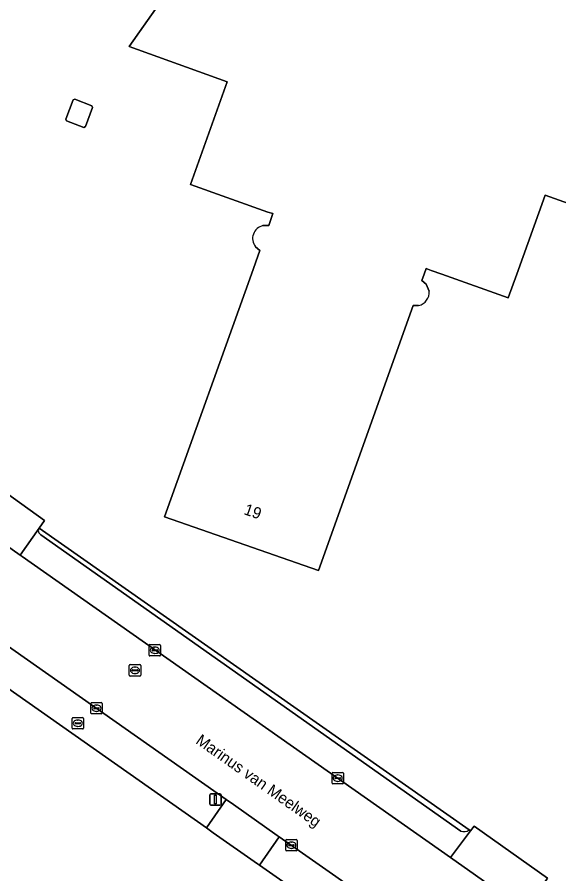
# Model space of a CAD drawing. Extents: x 155018 to 156648, y 383979 to 385733.
# Drawn here: x 155513.9 to 155561.5, y 384947.3 to 385022.6 of the extents above; entities that cross this region are included whole.
import ezdxf

# ---------------------------------------------------------------- set-up
doc = ezdxf.new("R2010")
doc.units = 0
for name, color, linetype in [('IMGEO_Brandkraan', 7, 'Continuous'), ('IMGEO_Erf', 7, 'Continuous'), ('IMGEO_Kolk', 7, 'Continuous'), ('IMGEO_Lichtmast', 7, 'Continuous'), ('IMGEO_Openbare_ruimte_label', 7, 'Continuous'), ('IMGEO_Pand', 7, 'Continuous'), ('IMGEO_Pand_nummerreeks', 7, 'Continuous'), ('IMGEO_Parkeervlak_open', 7, 'Continuous'), ('IMGEO_Rijbaan_lokaal_gesloten', 7, 'Continuous'), ('IMGEO_Rioolput', 7, 'Continuous'), ('IMGEO_Voetpad_open', 7, 'Continuous')]:
    doc.layers.add(name, color=color, linetype=linetype)

msp = doc.modelspace()

# ---------------------------------------------------------------- linework, layer by layer
at = {"layer": 'IMGEO_Brandkraan'}
for p, q in [((155518.686, 384960.086), (155518.686, 384960.938)), ((155518.761, 384961.012), (155519.613, 384961.012)), ((155518.945, 384960.506), (155518.945, 384960.518)), ((155518.988, 384960.555), (155519.386, 384960.555)), ((155519.174, 384960.792), (155519.199, 384960.792)), ((155519.429, 384960.518), (155519.429, 384960.506)), ((155519.687, 384960.938), (155519.687, 384960.086)), ((155519.613, 384960.012), (155518.761, 384960.012)), ((155519.383, 384960.469), (155518.985, 384960.469)), ((155519.197, 384960.232), (155519.172, 384960.232))]:
    msp.add_line(p, q, dxfattribs=at)
for points in [[(155518.686, 384960.086), (155518.686, 384960.938)], [(155518.761, 384961.012), (155519.613, 384961.012)], [(155519.687, 384960.938), (155519.687, 384960.086)], [(155519.613, 384960.012), (155518.761, 384960.012)]]:
    msp.add_lwpolyline(points, dxfattribs=at)
for centre, radius, start, end in [((155518.763, 384960.936), 0.0765, 91.55205, 178.44795), ((155518.763, 384960.936), 0.0765, 91.55205, 178.44795), ((155518.985, 384960.515), 0.0403, 85.87752, 175.75265), ((155518.982, 384960.505), 0.0366, 178.93798, 274.71019), ((155519.386, 384960.512), 0.043, 264.86636, 352.45326), ((155519.39, 384960.517), 0.0386, 1.73085, 96.63898), ((155519.611, 384960.936), 0.0765, 1.55205, 88.44795), ((155519.611, 384960.936), 0.0765, 1.55205, 88.44795), ((155518.763, 384960.088), 0.0765, 181.55205, 268.44795), ((155518.763, 384960.088), 0.0765, 181.55205, 268.44795), ((155519.611, 384960.088), 0.0765, 271.55205, 358.44795), ((155519.611, 384960.088), 0.0765, 271.55205, 358.44795)]:
    msp.add_arc(centre, radius, start, end, dxfattribs=at)
for centre, major_axis, ratio, start_param, end_param in [((155519.173, 384960.512), (-0.387, 0.002), 0.722429, 4.712389, 7.853982), ((155519.198, 384960.512), (-0.39, 0.002), 0.717154, 1.570796, 4.712389)]:
    msp.add_ellipse(centre, major_axis=major_axis, ratio=ratio, start_param=start_param, end_param=end_param, dxfattribs=at)
at = {"layer": 'IMGEO_Erf'}
for points in [[(155535.473, 385004.273), (155535.985, 385004.271), (155536.336, 385005.323), (155535.896, 385005.456), (155529.096, 385007.886), (155532.322, 385016.918), (155523.708, 385020.015), (155526.582, 385024.107), (155553.008, 385061.731), (155555.772, 385060.745), (155568.458, 385096.335), (155630.019, 385074.396), (155603.521, 385000)], [(155457.525, 385018.63), (155458.619, 385017.864), (155484.145, 385000), (155491.64, 384994.721), (155500, 384988.865), (155510.83, 384981.203), (155511.294, 384981.88), (155516.258, 384978.35), (155515.775, 384977.663), (155553.601, 384951.142), (155553.738, 384951.046), (155554.058, 384951.47), (155560.497, 384946.89), (155560.229, 384946.497), (155580.857, 384931.994), (155586.597, 384927.958), (155607.46, 384913.427), (155617.317, 384906.512), (155620.874, 384904.014), (155651.48, 384882.509)], [(155645.703, 384870.176), (155613.715, 384892.628), (155600.657, 384901.793), (155582.308, 384914.778), (155574.917, 384919.981), (155570.133, 384923.483), (155539.854, 384944.743), (155535.161, 384948.038), (155534.984, 384948.163), (155531.101, 384950.889), (155530.5, 384951.311), (155510.828, 384965.124), (155506.264, 384968.328), (155505.588, 384968.803), (155501.395, 384971.747), (155500, 384972.727), (155492.047, 384978.311), (155491.266, 384978.86), (155482.605, 384984.76), (155482.381, 384984.92), (155460.927, 385000), (155450.653, 385007.222)], [(155603.521, 385000), (155602.521, 384997.193), (155600.843, 384992.482), (155579.769, 385000), (155560.285, 385006.951), (155557.797, 385000), (155557.05, 384997.913), (155551.193, 385000), (155550.264, 385000.331), (155549.839, 385000.497), (155549.65, 385000), (155549.437, 384999.439), (155549.832, 384999.123), (155550.085, 384998.504)], [(155549.161, 384997.245), (155548.687, 384997.244), (155540.351, 384973.929), (155526.816, 384978.65), (155534.46, 385000), (155535.208, 385002.089), (155534.809, 385002.413)]]:
    msp.add_lwpolyline(points, dxfattribs=at)
msp.add_lwpolyline([(155519.719, 385012.905), (155518.205, 385013.48), (155518.128, 385013.619), (155518.771, 385015.316), (155518.938, 385015.371), (155520.419, 385014.813), (155520.474, 385014.663), (155519.862, 385012.978)], close=True, dxfattribs=at)
for centre, radius, start, end in [((155535.726, 385003.134), 1.166, 102.51087, 218.19709), ((155548.923, 384998.389), 1.168, 281.77899, 5.66994)]:
    msp.add_arc(centre, radius, start, end, dxfattribs=at)
at = {"layer": 'IMGEO_Kolk'}
for p, q in [((155525.454, 384966.504), (155525.454, 384967.356)), ((155525.529, 384967.43), (155526.381, 384967.43)), ((155526.455, 384967.356), (155526.455, 384966.504)), ((155525.713, 384966.924), (155525.713, 384966.936)), ((155526.151, 384966.887), (155525.753, 384966.887)), ((155525.756, 384966.973), (155526.154, 384966.973)), ((155525.965, 384966.65), (155525.94, 384966.65)), ((155525.942, 384967.21), (155525.967, 384967.21)), ((155526.197, 384966.936), (155526.197, 384966.924)), ((155526.381, 384966.43), (155525.529, 384966.43)), ((155520.325, 384961.408), (155520.325, 384962.26)), ((155520.4, 384962.334), (155521.252, 384962.334)), ((155520.813, 384962.114), (155520.838, 384962.114)), ((155521.326, 384962.26), (155521.326, 384961.408)), ((155521.252, 384961.334), (155520.4, 384961.334)), ((155520.584, 384961.828), (155520.584, 384961.84)), ((155521.022, 384961.791), (155520.624, 384961.791)), ((155520.627, 384961.877), (155521.025, 384961.877)), ((155520.836, 384961.554), (155520.811, 384961.554)), ((155521.068, 384961.84), (155521.068, 384961.828)), ((155541.547, 384955.257), (155541.547, 384956.109)), ((155541.622, 384956.183), (155542.474, 384956.183)), ((155542.548, 384956.109), (155542.548, 384955.257)), ((155541.806, 384955.677), (155541.806, 384955.689)), ((155542.244, 384955.64), (155541.846, 384955.64)), ((155541.849, 384955.726), (155542.247, 384955.726)), ((155542.058, 384955.403), (155542.033, 384955.403)), ((155542.035, 384955.963), (155542.06, 384955.963)), ((155542.29, 384955.689), (155542.29, 384955.677)), ((155542.474, 384955.183), (155541.622, 384955.183)), ((155537.472, 384949.363), (155537.472, 384950.215)), ((155537.547, 384950.289), (155538.399, 384950.289)), ((155537.96, 384950.069), (155537.985, 384950.069)), ((155538.473, 384950.215), (155538.473, 384949.363)), ((155538.399, 384949.289), (155537.547, 384949.289)), ((155537.731, 384949.783), (155537.731, 384949.795)), ((155538.169, 384949.746), (155537.771, 384949.746)), ((155537.774, 384949.832), (155538.172, 384949.832)), ((155537.983, 384949.509), (155537.958, 384949.509)), ((155538.215, 384949.795), (155538.215, 384949.783))]:
    msp.add_line(p, q, dxfattribs=at)
for points in [[(155525.454, 384966.504), (155525.454, 384967.356)], [(155525.529, 384967.43), (155526.381, 384967.43)], [(155526.455, 384967.356), (155526.455, 384966.504)], [(155526.381, 384966.43), (155525.529, 384966.43)], [(155520.325, 384961.408), (155520.325, 384962.26)], [(155520.4, 384962.334), (155521.252, 384962.334)], [(155521.326, 384962.26), (155521.326, 384961.408)], [(155521.252, 384961.334), (155520.4, 384961.334)], [(155541.547, 384955.257), (155541.547, 384956.109)], [(155541.622, 384956.183), (155542.474, 384956.183)], [(155542.548, 384956.109), (155542.548, 384955.257)], [(155542.474, 384955.183), (155541.622, 384955.183)], [(155537.472, 384949.363), (155537.472, 384950.215)], [(155537.547, 384950.289), (155538.399, 384950.289)], [(155538.473, 384950.215), (155538.473, 384949.363)], [(155538.399, 384949.289), (155537.547, 384949.289)]]:
    msp.add_lwpolyline(points, dxfattribs=at)
for centre, radius, start, end in [((155525.531, 384967.354), 0.0765, 91.55205, 178.44795), ((155525.531, 384967.354), 0.0765, 91.55205, 178.44795), ((155526.379, 384967.354), 0.0765, 1.55205, 88.44795), ((155526.379, 384967.354), 0.0765, 1.55205, 88.44795), ((155525.753, 384966.933), 0.0403, 85.87752, 175.75265), ((155525.75, 384966.923), 0.0366, 178.93798, 274.71019), ((155526.154, 384966.93), 0.043, 264.86636, 352.45326), ((155526.158, 384966.935), 0.0386, 1.73085, 96.63898), ((155525.531, 384966.506), 0.0765, 181.55205, 268.44795), ((155525.531, 384966.506), 0.0765, 181.55205, 268.44795), ((155526.379, 384966.506), 0.0765, 271.55205, 358.44795), ((155526.379, 384966.506), 0.0765, 271.55205, 358.44795), ((155520.402, 384962.258), 0.0765, 91.55205, 178.44795), ((155520.402, 384962.258), 0.0765, 91.55205, 178.44795), ((155521.25, 384962.258), 0.0765, 1.55205, 88.44795), ((155521.25, 384962.258), 0.0765, 1.55205, 88.44795), ((155520.402, 384961.41), 0.0765, 181.55205, 268.44795), ((155520.402, 384961.41), 0.0765, 181.55205, 268.44795), ((155520.624, 384961.837), 0.0403, 85.87752, 175.75265), ((155520.621, 384961.827), 0.0366, 178.93798, 274.71019), ((155521.025, 384961.834), 0.043, 264.86636, 352.45326), ((155521.029, 384961.839), 0.0386, 1.73085, 96.63898), ((155521.25, 384961.41), 0.0765, 271.55205, 358.44795), ((155521.25, 384961.41), 0.0765, 271.55205, 358.44795), ((155541.624, 384956.107), 0.0765, 91.55205, 178.44795), ((155541.624, 384956.107), 0.0765, 91.55205, 178.44795), ((155542.472, 384956.107), 0.0765, 1.55205, 88.44795), ((155542.472, 384956.107), 0.0765, 1.55205, 88.44795), ((155541.624, 384955.259), 0.0765, 181.55205, 268.44795), ((155541.624, 384955.259), 0.0765, 181.55205, 268.44795), ((155541.846, 384955.686), 0.0403, 85.87752, 175.75265), ((155541.843, 384955.676), 0.0366, 178.93798, 274.71019), ((155542.247, 384955.683), 0.043, 264.86636, 352.45326), ((155542.251, 384955.688), 0.0386, 1.73085, 96.63898), ((155542.472, 384955.259), 0.0765, 271.55205, 358.44795), ((155542.472, 384955.259), 0.0765, 271.55205, 358.44795), ((155537.549, 384950.213), 0.0765, 91.55205, 178.44795), ((155537.549, 384950.213), 0.0765, 91.55205, 178.44795), ((155538.397, 384950.213), 0.0765, 1.55205, 88.44795), ((155538.397, 384950.213), 0.0765, 1.55205, 88.44795), ((155537.549, 384949.365), 0.0765, 181.55205, 268.44795), ((155537.549, 384949.365), 0.0765, 181.55205, 268.44795), ((155537.771, 384949.792), 0.0403, 85.87752, 175.75265), ((155537.768, 384949.782), 0.0366, 178.93798, 274.71019), ((155538.172, 384949.789), 0.043, 264.86636, 352.45326), ((155538.176, 384949.794), 0.0386, 1.73085, 96.63898), ((155538.397, 384949.365), 0.0765, 271.55205, 358.44795), ((155538.397, 384949.365), 0.0765, 271.55205, 358.44795)]:
    msp.add_arc(centre, radius, start, end, dxfattribs=at)
for centre, major_axis, ratio, start_param, end_param in [((155525.941, 384966.93), (-0.387, 0.002), 0.722429, 4.712389, 7.853982), ((155525.966, 384966.93), (-0.39, 0.002), 0.717154, 1.570796, 4.712389), ((155520.812, 384961.834), (-0.387, 0.002), 0.722429, 4.712389, 7.853982), ((155520.837, 384961.834), (-0.39, 0.002), 0.717154, 1.570796, 4.712389), ((155542.034, 384955.683), (-0.387, 0.002), 0.722429, 4.712389, 7.853982), ((155542.059, 384955.683), (-0.39, 0.002), 0.717154, 1.570796, 4.712389), ((155537.959, 384949.789), (-0.387, 0.002), 0.722429, 4.712389, 7.853982), ((155537.984, 384949.789), (-0.39, 0.002), 0.717154, 1.570796, 4.712389)]:
    msp.add_ellipse(centre, major_axis=major_axis, ratio=ratio, start_param=start_param, end_param=end_param, dxfattribs=at)
at = {"layer": 'IMGEO_Lichtmast'}
for p, q in [((155530.797, 384953.402), (155530.797, 384954.202)), ((155530.797, 384954.202), (155530.797, 384953.402)), ((155530.897, 384954.302), (155531.687, 384954.302)), ((155531.687, 384954.302), (155530.897, 384954.302)), ((155531.787, 384954.202), (155531.787, 384953.402)), ((155531.787, 384953.402), (155531.787, 384954.202)), ((155531.687, 384953.302), (155530.897, 384953.302)), ((155530.897, 384953.302), (155531.687, 384953.302))]:
    msp.add_line(p, q, dxfattribs=at)
msp.add_lwpolyline([(155531.217, 384954.177), (155531.367, 384954.177), (155531.367, 384953.427), (155531.217, 384953.427), (155531.217, 384954.177)], dxfattribs=at)
for centre, start, end in [((155530.897, 384954.202), 90, 180), ((155530.897, 384954.202), 90, 180), ((155531.687, 384954.202), 0, 90), ((155531.687, 384954.202), 360, 90), ((155530.897, 384953.402), 180, 270), ((155530.897, 384953.402), 180, 270), ((155531.687, 384953.402), 270, 0), ((155531.687, 384953.402), 270, 0)]:
    msp.add_arc(centre, 0.1, start, end, dxfattribs=at)
at = {"layer": 'IMGEO_Pand'}
for points in [[(155568.458, 385096.335), (155555.772, 385060.745), (155553.008, 385061.731), (155526.582, 385024.107), (155523.708, 385020.015), (155532.322, 385016.918), (155529.096, 385007.886), (155535.896, 385005.456), (155536.336, 385005.323), (155535.985, 385004.271), (155535.473, 385004.273)], [(155550.085, 384998.504), (155549.832, 384999.123), (155549.437, 384999.439), (155549.65, 385000), (155549.839, 385000.497), (155550.264, 385000.331), (155551.193, 385000), (155557.05, 384997.913), (155557.797, 385000), (155560.285, 385006.951), (155579.769, 385000)], [(155534.809, 385002.413), (155535.208, 385002.089), (155534.46, 385000), (155526.816, 384978.65), (155540.351, 384973.929), (155548.687, 384997.244), (155549.161, 384997.245)]]:
    msp.add_lwpolyline(points, dxfattribs=at)
msp.add_lwpolyline([(155519.719, 385012.905), (155519.862, 385012.978), (155520.474, 385014.663), (155520.419, 385014.813), (155518.938, 385015.371), (155518.771, 385015.316), (155518.128, 385013.619), (155518.205, 385013.48)], close=True, dxfattribs=at)
for centre, radius, start, end in [((155535.726, 385003.134), 1.166, 102.51087, 218.19709), ((155548.923, 384998.389), 1.168, 281.77899, 5.66994)]:
    msp.add_arc(centre, radius, start, end, dxfattribs=at)
at = {"layer": 'IMGEO_Parkeervlak_open'}
for points in [[(155515.775, 384977.663), (155514.115, 384975.3), (155514.295, 384975.174), (155551.965, 384948.699), (155553.738, 384951.046), (155553.601, 384951.142)], [(155552.875, 384951.036), (155515.938, 384977.083)]]:
    msp.add_lwpolyline(points, dxfattribs=at)
for centre, radius, start, end in [((155516.12, 384977.447), 0.407, 147.91031, 243.48408), ((155553.157, 384951.645), 0.671, 245.15954, 311.45407)]:
    msp.add_arc(centre, radius, start, end, dxfattribs=at)
at = {"layer": 'IMGEO_Rijbaan_lokaal_gesloten'}
for points in [[(155650.099, 384879.818), (155615.524, 384904.073), (155605.603, 384911.034), (155580.666, 384928.528), (155558.57, 384944.057), (155551.965, 384948.699), (155514.295, 384975.174), (155514.115, 384975.3), (155509.167, 384978.777), (155500, 384985.217), (155489.982, 384992.256), (155489.845, 384992.352), (155482.635, 384997.401), (155478.917, 385000), (155456.1, 385015.949)], [(155452.478, 385009.864), (155466.537, 385000), (155468.855, 384998.374), (155481.303, 384989.599), (155484.226, 384987.538), (155493.798, 384980.798), (155500, 384976.456), (155502.879, 384974.44), (155503.149, 384974.25), (155507.358, 384971.292), (155508.017, 384970.829), (155512.594, 384967.613), (155532.25, 384953.8), (155532.882, 384953.356), (155536.732, 384950.651), (155536.91, 384950.526), (155541.6, 384947.23), (155571.894, 384925.942), (155573.015, 384925.172), (155576.741, 384922.577), (155602.522, 384904.454), (155615.591, 384895.277), (155647.55, 384872.837)]]:
    msp.add_lwpolyline(points, dxfattribs=at)
at = {"layer": 'IMGEO_Rioolput'}
for p, q in [((155523.716, 384964.738), (155523.716, 384965.59)), ((155523.791, 384965.664), (155524.643, 384965.664)), ((155523.975, 384965.158), (155523.975, 384965.17)), ((155524.413, 384965.121), (155524.015, 384965.121)), ((155524.018, 384965.207), (155524.416, 384965.207)), ((155524.204, 384965.444), (155524.229, 384965.444)), ((155524.459, 384965.17), (155524.459, 384965.158)), ((155524.717, 384965.59), (155524.717, 384964.738)), ((155524.643, 384964.664), (155523.791, 384964.664)), ((155524.227, 384964.884), (155524.202, 384964.884))]:
    msp.add_line(p, q, dxfattribs=at)
for points in [[(155523.716, 384964.738), (155523.716, 384965.59)], [(155523.791, 384965.664), (155524.643, 384965.664)], [(155524.717, 384965.59), (155524.717, 384964.738)], [(155524.643, 384964.664), (155523.791, 384964.664)]]:
    msp.add_lwpolyline(points, dxfattribs=at)
for centre, radius, start, end in [((155523.793, 384965.588), 0.0765, 91.55205, 178.44795), ((155523.793, 384965.588), 0.0765, 91.55205, 178.44795), ((155524.015, 384965.167), 0.0403, 85.87752, 175.75265), ((155524.012, 384965.157), 0.0366, 178.93798, 274.71019), ((155524.416, 384965.164), 0.043, 264.86636, 352.45326), ((155524.42, 384965.169), 0.0386, 1.73085, 96.63898), ((155524.641, 384965.588), 0.0765, 1.55205, 88.44795), ((155524.641, 384965.588), 0.0765, 1.55205, 88.44795), ((155523.793, 384964.74), 0.0765, 181.55205, 268.44795), ((155523.793, 384964.74), 0.0765, 181.55205, 268.44795), ((155524.641, 384964.74), 0.0765, 271.55205, 358.44795), ((155524.641, 384964.74), 0.0765, 271.55205, 358.44795)]:
    msp.add_arc(centre, radius, start, end, dxfattribs=at)
for centre, major_axis, ratio, start_param, end_param in [((155524.203, 384965.164), (-0.387, 0.002), 0.722429, 4.712389, 7.853982), ((155524.228, 384965.164), (-0.39, 0.002), 0.717154, 1.570796, 4.712389)]:
    msp.add_ellipse(centre, major_axis=major_axis, ratio=ratio, start_param=start_param, end_param=end_param, dxfattribs=at)
at = {"layer": 'IMGEO_Voetpad_open'}
for points in [[(155514.115, 384975.3), (155515.775, 384977.663), (155516.258, 384978.35), (155511.294, 384981.88), (155510.83, 384981.203), (155509.167, 384978.777)], [(155512.594, 384967.613), (155508.017, 384970.829), (155506.264, 384968.328), (155510.828, 384965.124), (155530.5, 384951.311), (155532.25, 384953.8)], [(155532.882, 384953.356), (155532.25, 384953.8), (155530.5, 384951.311), (155531.101, 384950.889), (155534.984, 384948.163), (155535.161, 384948.038), (155536.91, 384950.526), (155536.732, 384950.651)], [(155553.738, 384951.046), (155551.965, 384948.699), (155558.57, 384944.057), (155560.072, 384946.265), (155560.229, 384946.497), (155560.497, 384946.89), (155554.058, 384951.47)], [(155541.6, 384947.23), (155536.91, 384950.526), (155535.161, 384948.038), (155539.854, 384944.743), (155570.133, 384923.483), (155571.894, 384925.942)]]:
    msp.add_lwpolyline(points, close=True, dxfattribs=at)
for points in [[(155553.601, 384951.142), (155515.775, 384977.663)], [(155515.938, 384977.083), (155552.875, 384951.036)]]:
    msp.add_lwpolyline(points, dxfattribs=at)
for centre, radius, start, end in [((155516.12, 384977.447), 0.407, 147.91031, 243.48408), ((155553.157, 384951.645), 0.671, 245.15954, 311.45407)]:
    msp.add_arc(centre, radius, start, end, dxfattribs=at)

# ---------------------------------------------------------------- texts
at = {"layer": 'IMGEO_Openbare_ruimte_label'}
msp.add_text('Marinus van Meelweg', height=1, rotation=324.89531, dxfattribs=at).set_placement((155529.487, 384958.798))
at = {"layer": 'IMGEO_Pand_nummerreeks'}
msp.add_text('19', height=1, rotation=340.77126, dxfattribs=at).set_placement((155533.72, 384978.911))

doc.saveas('drawing.dxf')
